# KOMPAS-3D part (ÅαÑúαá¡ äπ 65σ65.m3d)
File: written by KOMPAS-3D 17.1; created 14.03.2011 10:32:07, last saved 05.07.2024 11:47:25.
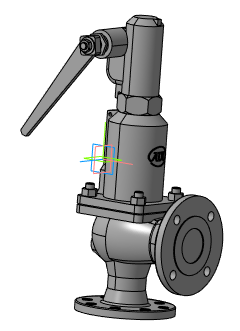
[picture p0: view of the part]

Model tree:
1. Операция без истории:2

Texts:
  Viktor2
